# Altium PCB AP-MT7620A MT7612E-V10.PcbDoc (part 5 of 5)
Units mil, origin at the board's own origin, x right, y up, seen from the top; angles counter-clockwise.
Board outline 4645.67 x 3740.16 mil, 4 copper layers (Top, Inner Layer 2, Inner Layer 3, Bottom), stack 35.4 mil thick; 603 components, 409 nets, 1850 pads, 2004 vias.
Unrouted connection lines stored in the file: 90.
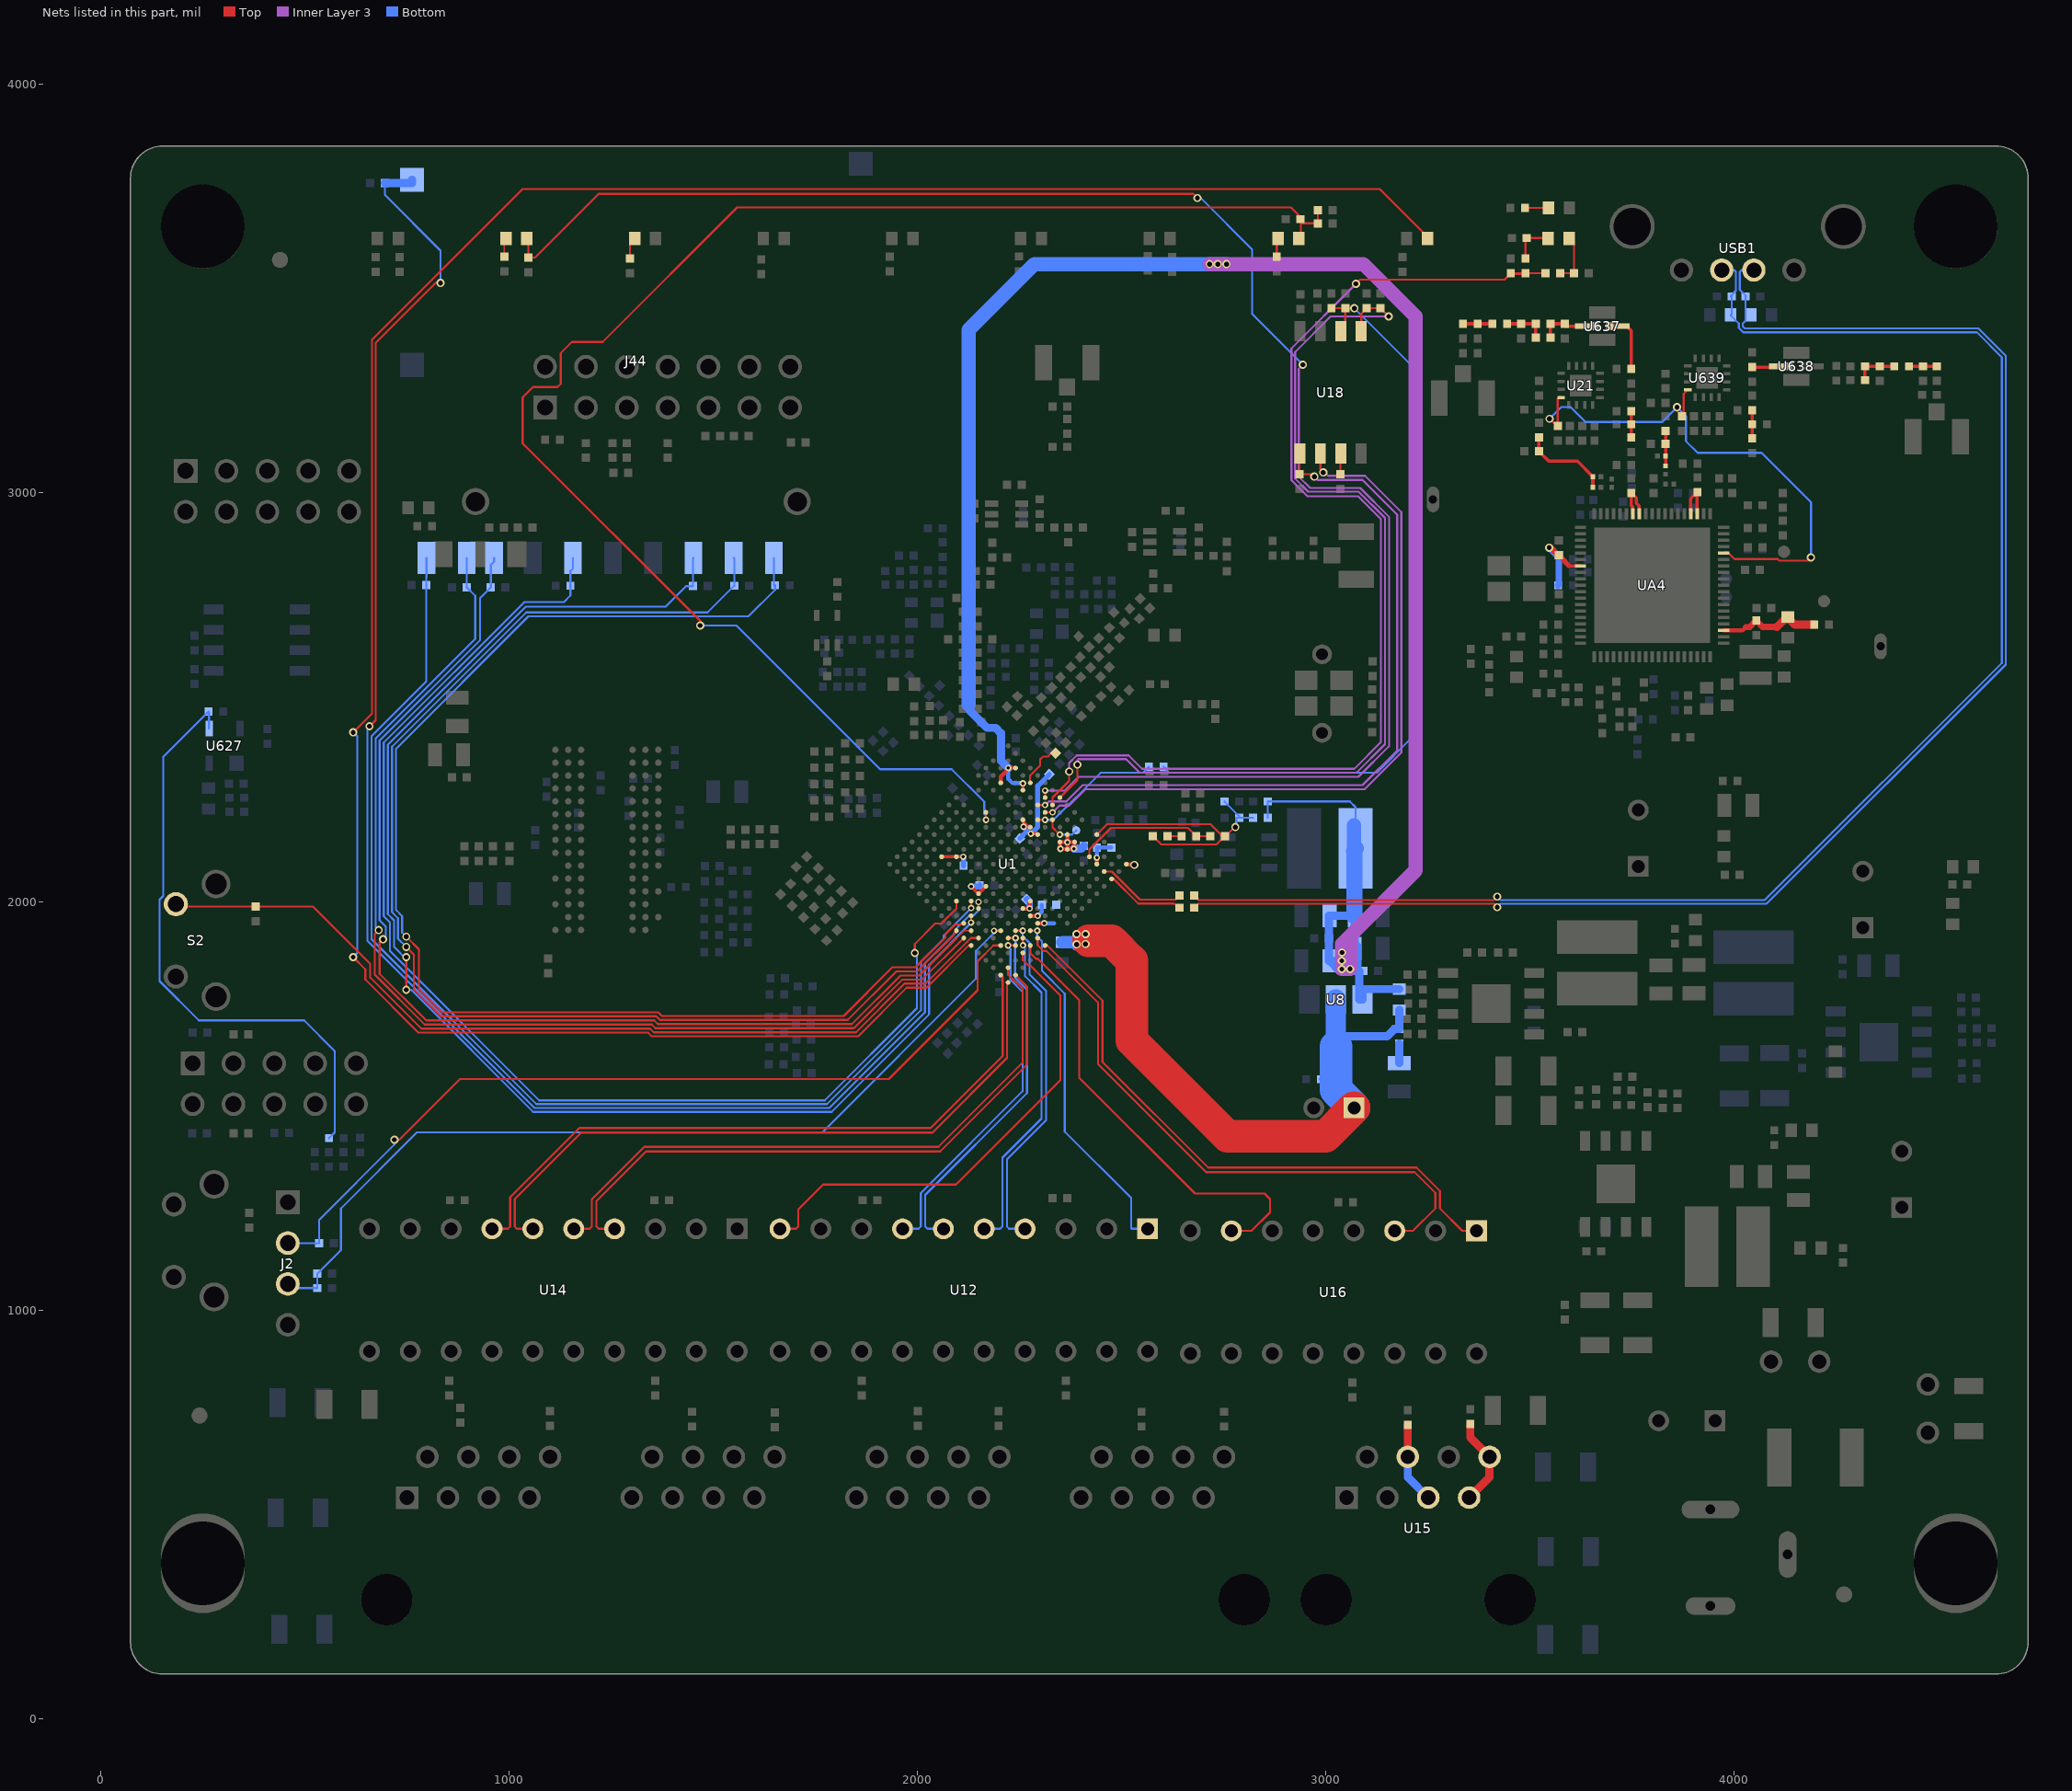
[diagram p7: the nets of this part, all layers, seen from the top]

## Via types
v1: diameter 20, hole 12, Top to Bottom, 1824 vias
v2: diameter 16, hole 8, Top to Bottom, 180 vias

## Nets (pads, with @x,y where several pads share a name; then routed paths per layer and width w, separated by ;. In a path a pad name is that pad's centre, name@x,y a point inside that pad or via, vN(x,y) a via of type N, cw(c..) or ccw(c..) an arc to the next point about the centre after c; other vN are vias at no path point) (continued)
RXIP2: U1.P16 U12.10 | length 1213.5
  Top w5: U12.10@1664,1199 1703,1199 1708.5,1204.5 1708.5,1246.28 1769.68,1307.45 2094.68,1307.45 2350.25,1563.03 2350.25,1769.97 2277.93,1842.29 2273.21,1842.29 2258.69,1856.81 U1.P16@2258.69,1874.36
RXIP3: U1.M15 U12.1 | length 881.4
  Top w5: U1.M15@2276.79,1928.64 v2(2293.72,1928.64)
  Bottom w5: v2(2293.72,1928.64) 2293.72,1913.94 2305.19,1902.47 2305.19,1830.54 2361.26,1774.47 2361.26,1748.84 2361.25,1436.81 2523.71,1274.35 2523.71,1200.29 2525,1199 U12.1@2564,1199
RXIP4: U1.N16 U16.7 | length 1111.7
  Top w5: U1.N16@2276.79,1892.45 2276.79,1874.09 2290.78,1860.09 2295.13,1860.09 2396.25,1758.97 2396.25,1568.97 2680.1,1285.12 2850.1,1285.12 2863.5,1271.72 2863.5,1239.09 2818.41,1194 U16.7@2769,1194
S_COMP: C37.2 R26.1 | length 34
  Top w5: R26.1@2613,2160 C37.2@2647,2160
SD_CD: J44.CD R388.2 U1.P9 | length 2914.9
  Top w5: v2(2132,1984) U1.P9@2132.02,2001.02
  Bottom w5: R388.2@798.61,2775.61 R388.2@798,2775 ; J44.CD@798.61,2841 798.61,2793.62 798,2793.01 R388.2@798,2775 ; v2(2132,1984) 2065,1917 2065,1909 2009,1853 2009,1734 1779.34,1504.34 1067.66,1504.34 664,1908 664,2405 798,2539 R388.2@798,2775
SD_CLK: C275.1 J44.5 U1.R8 | length 3066.7
  Top w5: v1(1994,1874) 1994,1896.03 2043.85,1945.88 2058.88,1945.88 2095.83,1982.83 U1.R8@2095.83,2001.02
  Bottom w5: J44.5@1156.87,2841 1156.87,2814.87 1151,2809 C275.1@1151,2773 1151,2749 1135.08,2733.08 1038.08,2733.08 694,2389 694,1964 709,1949 709,1879 1074.57,1513.43 1773.43,1513.43 1999,1739 1999,1869 v1(1994,1874)
SD_CMD: J44.2 R377.2 U1.R10 | length 3391.9
  Top w5: v1(749,1784) v1(749,1864) ; v2(2131.9,1948.5) U1.R10@2132.02,1964.83
  Bottom w5: v1(749,1784) 761.24,1784 1059.92,1485.32 1790.32,1485.32 2029,1724 2029,1845.6 v2(2131.9,1948.5) ; v1(749,1864) 749,1859 719,1889 719,1954 704,1969 704,2384 1041.87,2721.87 1384.1,2721.87 1434.23,2772 R377.2@1451,2772 1451,2839.85 J44.2@1452.15,2841
SD_D0: J44.7 R376.2 U1.T11 | length 2740
  Top w4: 2096,1910 2115,1928.64 U1.T11@2132.02,1928.64
  Top w5: v1(692.04,1907.46) 684,1899.42 684,1823 798,1709 1356,1709 1365,1700 1840,1700 1959,1819 2005,1819 2096,1910
  Bottom w5: v1(692.04,1907.46) 699,1914.42 699,1939 684,1954 684,2394 930,2640 930,2743 R376.2@956,2769 956,2824 963.96,2831.96 J44.7@963.96,2841
SD_D1: J44.8 R375.2 U1.U11 | length 2724.7
  Top w5: v1(681.64,1930.04) 671.71,1920.11 671.71,1821.29 794,1699 1350,1699 1359,1690 1845,1690 1964,1809 2012.38,1809 U1.U11@2113.93,1910.55
  Bottom w5: v1(681.64,1930.04) 674,1937.68 674,2399 918,2643 918,2748 R375.2@897,2769 897,2790.3 ; 897.03,2790.33 J44.8@897.03,2841
SD_D2: J44.9 R371.2 U1.T10 | length 3243
  Top w5: v1(749,1914) 780,1883 780,1785.65 836.65,1729 1366,1729 1375,1720 1820,1720 1939,1839 1996,1839 2069,1912 2069,1920 2093,1944 2113.93,1944 U1.T10@2113.93,1946.74
  Bottom w5: v1(749,1914) 739,1924 739,1964 724,1979 724,2374 1047.82,2697.82 1586.82,2697.82 1652,2763 R371.2@1652,2774 1649,2774 J44.9@1649,2841
SD_D3: J44.1 R373.2 U1.U10 | length 3137.9
  Top w5: v1(749,1889) 767.36,1870.64 767.36,1785.55 833.91,1719 1361,1719 1370,1710 1830,1710 1949,1829 2000.01,1829 2089,1918 2089,1921.81 U1.U10@2095.83,1928.64
  Bottom w5: v1(749,1889) 729,1909 729,1959 714,1974 714,2379 1042.6,2707.6 1486.6,2707.6 R373.2@1552,2773 1552,2839.57 J44.1@1550.57,2841
SD_WP: J44.WP R389.2 U1.P10 | length 4043.8
  Top w5: v1(659,2429) 659.23,2429 674,2443.77 674,3367 821,3514 v1(833,3514) ; v2(2150,1999) 2150.12,1998.88 U1.P10@2150.12,1982.93
  Bottom w5: v1(659,2429) 654,2424 654,1904 1063.21,1494.79 1784.79,1494.79 2018.9,1728.9 2018.9,1849.2 2095.7,1926 2095.7,1933.7 2128.25,1966.25 2138.25,1966.25 2150,1978 v2(2150,1999) ; R389.2@697,3758.5 697,3729 833,3593 v1(833,3514)
  Bottom w20: R389.2@697,3758.5 763.17,3758.5 J44.WP@763.17,3766.2
SECLED: D20.1 R370.1 R824.2 | length 104.9
  Top w5: R824.2@3489,3574 3489,3621 R370.1@3492,3624 3540.47,3624 3540.47,3622.78 D20.1@3544.41,3622.78
SECU_LED: D20.2 R823.2 R825.1 | length 126.2
  Top w5: R823.2@3574,3538 R825.1@3608,3538 3608,3614.31 3599.53,3622.78 D20.2@3595.59,3622.78
SFLASH_CLK: SR1.1 U1.D8 | length 326
  Top w5: U1.D8@2294.88,2200.04 v2(2313.13,2200)
  Bottom w5: v2(2313.13,2200) 2333.6,2200 2448.64,2315.04 2552.04,2315.04 SR1.1@2567,2330
SMPS_3V3_IN: CA36.1 CA37.1 RA21.1 UA4.41 | length 257.7
  Top w10: UA4.41@3974.2,2663.76 4020.68,2663.76 4028.19,2671.27
  Top w15: 4028.19,2671.27 4028.63,2671.71 4038.02,2671.71 4054,2687.69 4054,2687.56 CA36.1@4054.14,2687.56 4069.46,2672.23 4104.67,2672.23
  Top w20: 4104.67,2672.23 4129.16,2696.73 CA37.1@4131.16,2696.73 4131.16,2694.58 4131.01,2694.58 4147.59,2678 RA21.1@4196,2678
SOC_1.2VD: C7.1 C42.1 C43.1 C44.1 C50.1 C72.1 C166.1 C167.1 C210.1 R23.1 R55.1 R829.1 R830.1 U1.A17 U1.C11 U1.C12 U1.D11 U1.D12 U1.E7 U1.E8 U1.E9 U1.K13 U1.L13 U1.L14 U1.L15 U1.M5 U1.M9 U1.N4 U1.N9 U8.2 | length 2368.2
  Top w5: U1.L14@2276.79,1964.83 2277.24,1965.28 U1.L14@2277.75,1965.28
  Top w8: U1.N4@2059.64,2109.6 U1.M5@2095.83,2109.6 2112.4,2109.6 v2(2112.5,2109.5) ; v2(2132,2037) 2131.24,2037 2131.64,2036.62 U1.N9@2150.12,2019.12 U1.M9@2168.21,2037.21 ; U1.E7@2258.69,2200.07 2261,2197.76 2261,2194 ; U1.E8@2276.79,2181.98 2275.76,2183 U1.E8@2272,2183 ; v2(2278,2166) 2292.76,2166 U1.E9@2294.88,2163.88 ; U1.L15@2294.88,1946.74 U1.L15@2294.88,1946.87 ; v2@2311,1946.87 v2(2311,1947) ; 2261,2194 U1.E8@2272,2183 ; 2261,2194 v2(2260.3,2183) U1.E8@2272,2183
  Top w10: U1.L13@2258.69,1982.96 v2(2275,1983) ; v2(2275,1983) 2275.89,1983 2275.89,2001.02 U1.K13@2276.79,2001.02 ; U1.L14@2276.79,1964.83 2286.19,1964.83 2286.36,1965 v2(2295,1965) ; U1.L15@2294.88,1946.87 v2@2311,1946.87 ; U1.C11@2367.26,2163.88 2367.4,2163.88 v2@2367.4,2145.39 ; U1.A17@2512.02,2091.5 2512.02,2090.49 2531.33,2090.49 v1(2531.33,2089.48) ; U1.D11@2349.89,2145.39 2349.89,2129.09 v2(2350.61,2129.09) 2350.61,2128.39 U1.D12@2367.26,2128.39 ; U1.D11@2349.89,2145.39 2349.17,2145.39 U1.D11@2349.17,2145.79 2349.89,2145.79 U1.D11@2349.89,2145.39 ; U1.D11@2349.89,2145.39 v2@2367.4,2145.39 ; U1.D12@2367.26,2128.39 U1.D12@2367.26,2127.69 2367.4,2127.69 U1.D12@2367.4,2128.52 ; U1.D12@2367.26,2128.39 2367.26,2128.52 U1.D12@2367.4,2128.52 ; U1.D12@2367.4,2128.52 2383.56,2128.52 v2(2383.56,2129.35) 2384.46,2129.35 U1.C12@2384.46,2145.39 ; U1.D12@2367.4,2128.52 v2@2367.4,2144.99 ; v2@2367.4,2144.99 v2@2367.4,2145.39 ; v2@2367.4,2144.99 v2(2367.55,2144.99) v2@2367.55,2145.39 ; v2@2367.4,2145.39 v2@2367.55,2145.39 ; v2@2367.55,2145.39 U1.C12@2384.46,2145.39 ; U1.C12@2384.46,2145.39 2384.46,2145.79 U1.C12@2385.36,2145.79 2385.36,2145.39 U1.C12@2384.46,2145.39
  Top w20: v1(2412,1896) 2412,1897 2419.21,1904.21
  Top w80: 2419.21,1904.21 2475.92,1904.21 2525,1855.13 2525,1660 2760,1425 2999.21,1425 C7.1@3069.21,1495
  Bottom w10: v2(2295,1965) 2305,1975 C167.1@2305,1992 ; v2(2311,1947) 2335,1947 ; C50.1@2988,1565 3009.77,1543.23 3020.98,1543.23 3025,1539.21
  Bottom w12: v2(2112.5,2109.5) 2113.5,2108.5 C72.1@2113.5,2087.5 ; C44.1@2251.23,2154.27 2270,2173.04 2270,2174 ; v2(2260.3,2183) 2270,2174 ; R23.1@2323.27,2311.27 2294.87,2282.87 2294.87,2182.87 v2(2278,2166) 2270,2174
  Bottom w15: v2(2132,2037) 2151,2037 C43.1@2152.5,2039.5 ; R55.1@2267.53,2004.93 2268.72,2006.12 2275,1999.85 v2(2275,1983)
  Bottom w20: v2(2383.56,2129.35) 2401.35,2129.35 C210.1@2408,2136 ; 3025,1675 3030,1670 3150,1670 3168,1688 R829.1@3180,1688 R830.1@3180,1734.41
  Bottom w30: C42.1@2355,1900.59 2390,1900.59 v1(2390,1895)
  Bottom w50: 3025,1645 3025,1675 U8.2@3025,1760
  Bottom w80: 3025,1645 3025,1539.21 C7.1@3069.21,1495
  other v1: 2390,1920 2412,1920
SOC_1.5VD: C31.1 C32.1 C33.1 C34.1 C46.1 C55.1 C56.1 C97.1 C103.1 L4.2 R21.1 R830.2 U1.B3 U1.C5 U1.D3 U8.3 | length 5643.6
  Top w8: U1.D3@2203.16,2291.79 U1.D3@2204.4,2290.55 ; v2(2258.6,2289) 2258.69,2288.91 U1.C5@2258.69,2272.45
  Top w10: U1.D3@2204.4,2290.55 2204.4,2305.66 2224.25,2325.51 v2(2223.02,2326.74) U1.B3@2240.6,2326.74
  Inner Layer 3 w30: v1(3039.43,1854.87) 3059.28,1835.02 3059.53,1834.77 v1@3059.65,1834.9
  Inner Layer 3 w35: v1(2715.58,3559.99) v1(2735.59,3559.99) v1(2757,3560) 3092,3560 3220,3432 3220,2076.23 3059.77,1916 ; v1(3039.43,1854.87) 3039.43,1895.66 3059.77,1916 ; v1(3039.43,1854.87) v1(3039.43,1834.8) 3049.49,1834.8 3049.71,1835.02 3059.28,1835.02 v1@3059.53,1835.02 ; v1(3039.43,1854.87) 3039.55,1854.99 3049.59,1844.96 v1@3059.53,1835.02 ; v1@3059.53,1835.02 v1(3059.77,1835.02) ; v1@3059.53,1835.02 3059.65,1834.9 v1(3059.77,1835.02) ; v1(3059.77,1835.02) 3059.77,1916
  Bottom w5: R21.1@2858,2205 C31.1@2858,2245 3058.92,2245 3072.99,2230.93 L4.2@3072.99,2130 ; v1(3039.43,1834.8) 3041.2,1834.8 v1@3046,1830 ; v1(3039.43,1854.87) v1@3039.55,1854.99 ; v1@3059.65,1834.9 v1(3059.77,1835.02)
  Bottom w10: v2(2223.02,2326.74) 2223.02,2299.95 2233.47,2289.5 2258.6,2289.5 v2(2258.6,2289)
  Bottom w20: 2125.5,2483 2127,2481.5 2127,2469 2171,2425 2192,2425 2205,2412 C103.1@2205,2400 C97.1@2205,2367.5 2205,2344.76 v2(2223.02,2326.74) ; v1(3039.43,1834.8) v1(3039.43,1854.87) C56.1@3009.58,1854.87 ; v1@3039.55,1854.99 v1@3059.65,1834.9 ; R830.2@3180,1785.59 3090,1785.59 U8.3@3090,1760 3082,1760 3082,1830 3077.55,1830 ; C56.1@3009.45,1855 C56.1@3009.58,1854.87 ; C56.1@3009.45,1855 3008,1855 C32.1@3008,1910 3008,1965 C33.1@3009.45,1965 C46.1@3070.55,1965 C34.1@3070.55,1885 3077.55,1885 3077.55,1830 ; C56.1@3009.45,1855 3009.45,1854.87 C56.1@3009.58,1854.87 ; C56.1@3009.58,1854.87 3034.45,1830 3046,1830 3077.55,1830
  Bottom w35: 2125.5,2483 2125.5,3398.71 2286.79,3560 v1(2715.58,3559.99) v1(2735.59,3559.99) v1(2757,3560) ; L4.2@3069.5,2186 L4.2@3069.5,2125.34 ; C34.1@3070.5,1884.95 C34.1@3070.55,1885 C34.1@3071.55,1886 ; L4.2@3072.99,2130 3070.55,2126.75 L4.2@3069.5,2125.34 ; L4.2@3069.5,2125.34 3066.99,2122 3069.5,2124.51 L4.2@3069.5,2125.34
  Bottom w40: C46.1@3070.55,1965 3070.55,2126.75 3070.55,2127.56 L4.2@3072.99,2130
  other v1: 3040,1875
SOC_COMP: C37.1 C38.1 U1.C14 | length 343.6
  Top w5: U1.C14@2421.55,2109.6 2421.55,2127.55 2474.17,2180.17 2662.83,2180.17 C37.1@2683,2160 C38.1@2717,2160
SOC_FB: C38.2 R21.2 R22.2 R24.1 R26.2 U1.A13 | length 686.5
  Top w5: U1.A13@2439.64,2163.88 2464.93,2189.17 2718,2189.17 2747.17,2160 C38.2@2753,2160 ; R26.2@2577,2160 2597,2140 2733,2140 C38.2@2753,2160 ; v1(2778.86,2182.19) 2777.94,2183.11 2753.92,2159.08 2753,2159.08 C38.2@2753,2160
  Bottom w5: R22.2@2752,2245 2788,2209 R24.1@2788,2205 ; v1(2778.86,2182.19) 2781.15,2182.19 2781.15,2205 R24.1@2788,2205 ; R21.2@2822,2205 R24.1@2788,2205
SPI_CLK: R125.2 R127.2 SR1.2 U18.6 | length 1874.3
  Top w5: R125.2@3014,3452 R127.2@3048,3452 ; U18.6@3037,3395.8 3048,3406.8 R127.2@3048,3452 ; v1(3070,3452) R127.2@3048,3452
  Bottom w5: SR1.2@2603,2330 2618,2315 3125,2315 3209,2399 3209,3313 v1(3070,3452)
SPI_CS0: R170.1 U1.C7 U18.1 | length 1843.3
  Top w5: U1.C7@2294.88,2236.26 2294.88,2236.18 2313.14,2236.18 v2(2313.14,2236.11) ; U18.1@2937,3096.2 2936,3095.2 R170.1@2936,3046 2966,3046 v1(2972,3040)
  Inner Layer 3 w5: v2(2313.14,2236.11) 2322.04,2245 2365,2245 2405,2285 3090,2285 3175,2370 3175,2946.91 3089.91,3032 2980,3032 v1(2972,3040)
SPI_CS1: TP601.1 U1.C9 | length 88.7
  Top w5: U1.C9@2331.07,2200.07 2331.07,2181.5 2345.57,2167 2349,2165.07 v2(2349,2164)
  Bottom w5: v2(2349,2164) 2379.13,2164 TP601.1@2389.39,2174.26
SPI_HOLD: R142.2 R823.1 R824.1 U1.B8 | length 2792.2
  Top w5: U1.B8@2331.07,2236.26 2331.07,2254.36 2372,2295.29 v1(2372,2318) ; v1(3074,3512) 3084,3522 3438,3522 3452,3536 3487,3536 R824.1@3489,3538 ; R142.2@3453,3538 R824.1@3489,3538 ; R823.1@3538,3538 R824.1@3489,3538
  Inner Layer 3 w5: v1(2372,2318) 2372,2339 2390.53,2357.53 2517.47,2357.53 2550,2325 3070,2325 3135,2390 3135,2936 3079,2992 2955.27,2992 2916,3031.27 2916,3354 v1(3074,3512)
SPI_MISO: U1.C8 U18.2 | length 1801.1
  Top w5: U1.C8@2312.98,2218.17 2314.81,2218.2 v2(2331.2,2218.2) ; U18.2@2987,3096.2 2987,3057 v1(2994,3050)
  Inner Layer 3 w5: v2(2331.2,2218.2) 2348,2235 2371.8,2235 2411.8,2275 3095,2275 3185,2365 3185,2953 3096,3042 3006,3042 2998,3050 v1(2994,3050)
SPI_MOSI: R133.2 R135.2 U1.A8 U18.5 | length 2423.8
  Top w5: U1.A8@2349.17,2254.36 2392,2297.19 v1(2392,2335) ; U18.5@3082,3395.8 U18.5@3087,3395.8 3087,3439 R135.2@3100,3452 R133.2@3134,3452 v1(3154,3432)
  Inner Layer 3 w5: v1(2392,2335) 2392,2345.93 2394.58,2348.51 2511.49,2348.51 2545,2315 3075,2315 3145,2385 3145,2938.73 3080.73,3003 2957,3003 2925,3035 2925,3345 3012,3432 v1(3154,3432)
SPI_WP: D26.2 R136.2 U1.B7 | length 4282.8
  Top w5: D26.2@1044.47,3622.78 1048.41,3622.78 1048,3622.37 R136.2@1048,3576 1064,3576 1220,3732 2676,3732 v1(2686,3722) ; U1.B7@2312.98,2254.36 2313.08,2254.36 2313.08,2271.57 v2(2313.18,2271.57)
  Inner Layer 3 w5: v2(2313.18,2271.57) 2324.05,2271.57 2324.12,2271.5 2361.5,2271.5 2395,2305 3080,2305 3155,2380 3155,2941.46 3084.46,3012 2962,3012 2934,3040 2934,3304 v1(2944,3314)
  Bottom w5: v1(2686,3722) 2694,3722 2820,3596 2820,3438 v1(2944,3314)
TRSW_P: C159.2 C161.2 U21.4 U639.4 UA4.53 | length 1381.5
  Top w5: v1(3547.97,3181.47) 3564.93,3164.51 3567.49,3164.51 C159.2@3568,3164 3568,3230.62 3570.85,3233.47 3571.47,3233.47 U21.4@3570,3232 ; v1(3860,3210) 3858,3210 3858,3202 C161.2@3872,3188 3876.47,3192.47 3876.47,3202.53 3876.42,3202.58 3876.42,3242.63 U639.4@3886.26,3252.47 ; UA4.53@3974.2,2852.74 3974.2,2854 3984.9,2854 4000.9,2838 4106.29,2838 4110.29,2834 4180,2834 v1(4188,2842)
  Top w8: U21.4@3571.47,3233.47 U21.4@3576.26,3233.47
  Bottom w5: v1(3547.97,3181.47) 3576.49,3210 3600,3210 3636.13,3173.87 3823.87,3173.87 v1(3860,3210) 3882,3188 3882,3126.67 3910.67,3098 4067,3098 4188,2977 v1(4188,2842)
TXOM0: U1.U17 U14.6 | length 1649.9
  Top w5: U14.6@1059,1199 1020,1199 1014.5,1204.5 1014.5,1271.72 1177.45,1434.67 2037.45,1434.67 2220,1617.22 2220,1801.98 U1.U17@2222.5,1801.98
TXOM1: U1.T17 U14.4 | length 1532.6
  Top w5: U14.4@1259,1199 1220,1199 1214.5,1204.5 1214.5,1266.72 1336.15,1388.37 2056.15,1388.37 2268.81,1601.03 2268.81,1791.97 2240.65,1820.13 U1.T17@2240.6,1820.07
TXOM2: U1.P15 U12.7 | length 872.1
  Top w5: v2(2222.45,1892.55) 2231.1,1892.55 2231.19,1892.45 U1.P15@2240.6,1892.45
  Bottom w5: U12.7@1964,1199 2003,1199 2008.5,1204.5 2008.5,1286.6 2257.83,1535.93 2257.83,1779.19 2228.5,1808.52 2228.5,1883.75 2221.08,1891.18 v2(2222.45,1892.55)
TXOM3: U1.N14 U12.4 | length 851.9
  Top w5: U1.N14@2240.6,1928.64 2250,1928.64 v2(2258.4,1928.65)
  Bottom w5: v2(2258.4,1928.65) 2258.4,1915.38 2275,1898.78 2275,1821.79 2315.23,1781.56 2315.23,1464.23 2219.5,1368.5 2219.5,1204.5 2225,1199 U12.4@2264,1199
TXOM4: U1.M17 U16.1 | length 1458.4
  Top w5: U1.M17@2312.98,1892.45 2318.33,1892.45 2453.46,1757.32 2453.46,1607.32 2712.05,1348.73 3222.05,1348.73 3279.5,1291.28 3279.5,1249 3334.5,1194 U16.1@3369.39,1194
TXOP0: U1.U16 U14.7 | length 1667.4
  Top w5: U14.7@959,1199 998,1199 1003.5,1204.5 1003.5,1276.28 1172.89,1445.67 2032.89,1445.67 2209,1621.78 2209,1815.48 U1.U16@2204.4,1820.07
TXOP1: U1.T16 U14.5 | length 1554.8
  Top w5: U14.5@1159,1199 1198,1199 1203.5,1204.5 1203.5,1271.28 1331.59,1399.37 2051.59,1399.37 2257.81,1605.59 2257.81,1787.41 2239.78,1805.44 2237.68,1805.44 2222.5,1820.62 U1.T16@2222.5,1838.17
TXOP2: U1.P14 U12.6 | length 887
  Top w5: U1.P14@2222.5,1910.55 v2(2240.73,1910.55)
  Bottom w5: U12.6@2064,1199 2025,1199 2019.5,1204.5 2019.5,1282.04 2268.83,1531.37 2268.83,1783.76 2239.5,1813.09 2239.5,1889.05 2240.73,1890.28 v2(2240.73,1910.55)
TXOP3: U1.N15 U12.5 | length 811.3
  Top w5: U1.N15@2258.69,1910.55 2258.69,1897.51 2258.83,1897.36 v2(2258.83,1892.73)
  Bottom w5: U12.5@2164,1199 2203,1199 2208.5,1204.5 2208.5,1373.06 2304.23,1468.79 2304.23,1777 2264,1817.23 2264,1887.56 v2(2258.83,1892.73)
TXOP4: U1.M16 U16.3 | length 1490.2
  Top w5: U1.M16@2294.88,1910.55 2294.88,1893 2308.75,1879.14 2316.09,1879.14 2442.45,1752.77 2442.45,1602.77 2707.49,1337.73 3217.49,1337.73 3268.5,1286.72 3268.5,1249 3213.5,1194 U16.3@3169,1194
UART_RX: J2.2 R54.1 U1.R14 | length 2129.2
  Top w5: v1(720,1417) 732,1417 880.5,1565.5 1928.23,1565.5 1928.3,1565.57 1930.57,1565.57 2147.69,1782.69 2147.69,1853.69 2186.46,1892.46 U1.R14@2204.41,1892.46
  Bottom w5: J2.2@459,1164 R54.1@536,1164 536,1221 720,1405 v1(720,1417)
UART_TX: J2.3 R137.2 R139.2 U1.P13 | length 2237.9
  Top w5: v2(2188,1928.5) U1.P13@2204.4,1928.64
  Bottom w5: J2.3@459,1064 459,1059 464,1054 R139.2@531,1054 R137.2@531,1089 589,1147 589,1249 775,1435 1767.74,1435 2144,1811.26 2144,1879 2188,1923 v2(2188,1928.5)
UPHY0_PADM: R815.2 U1.C16 | length 217.4
  Top w5: U1.C16@2457.74,2073.4 2476.33,2073.4 2544.99,2004.75 2632.5,2004.75 2642,2014.25 R815.2@2642,2015
UPHY0_PADM_0: D3.2 R815.1 UC1.1 USB1.2 | length 3840.9
  Top w5: R815.1@2678,2015 2689.31,2003.69 3333.81,2003.69 3333.87,2003.75 3411.75,2003.75 v1(3420,2012)
  Bottom w5: v1(3420,2012) 3428.25,2003.75 4075.03,2003.75 4655.25,2583.97 4655.25,3332.07 4594.21,3393.1 4022.18,3393.1 4011.25,3404.03 4011.25,3414.5 3992,3433.75 D3.2@3992,3435.59 ; USB1.2@3969.4,3545.58 3969.67,3545.62 3999.67,3545.62 4004.29,3541 4004.29,3494.83 3992.23,3482.77 3992.23,3481 UC1.1@3994,3481 3994,3437.59 D3.2@3992,3435.59 ; D3.2@3991.59,3436 D3.2@3992,3435.59
UPHY0_PADP: R814.2 U1.C17 | length 197.4
  Top w5: U1.C17@2475.83,2055.31 2480.99,2055.31 2541.05,1995.25 2628.71,1995.25 2640.48,1983.48 2642,1983.48 R814.2@2642,1985
UPHY0_PADP_0: D4.2 R814.1 UC2.1 USB1.3 | length 3849.8
  Top w5: R814.1@2678,1985 2687.19,1994.19 3356.68,1994.19 3356.74,1994.25 3411.75,1994.25 v1(3420,1986)
  Bottom w5: v1(3420,1986) 3428.25,1994.25 4078.97,1994.25 4664.75,2580.03 4664.75,3336 4598.15,3402.6 4026.11,3402.6 4020.75,3407.97 4020.75,3414.5 4028,3421.75 UC2.1@4028,3481 4029.09,3481 4029.09,3482.09 4013.79,3497.4 4013.79,3541 4018.41,3545.62 USB1.3@4048.41,3545.62
UPHY0_VRES: C69.2 R51.1 U1.C15 | length 75.9
  Top w10: U1.C15@2439.64,2091.5 v2(2439.62,2107.43)
  Bottom w10: v2(2439.62,2107.43) 2439.62,2132 C69.2@2440,2132 R51.1@2475,2132
USB_IND_LED: D13.2 U1.U12 | length 6033.6
  Top w5: v1(619,1864) 649,1834 649,1809 779,1679 1341,1679 1350,1670 1855,1670 1974,1789 2022.66,1789 2126.11,1892.45 U1.U12@2132.02,1892.45 ; v1(619,2414) 665,2460 665,3375 1034,3744 3131.92,3744 3253.14,3622.78 D13.2@3249.2,3622.78
  Bottom w5: v1(619,1864) 629,1874 629,2404 v1(619,2414)
V12: C48.1 R829.2 | length 47.6
  Bottom w20: C48.1@3180,1604.45 R829.2@3180,1652 R829.2@3180.05,1651.95
WAN_C1: R122.1 U15.4 U15.5 | length 198.7
  Top w20: U15.4@3201,641 R122.1@3201,719
  Bottom w20: U15.4@3201,641 3201,591 U15.5@3251,541
WAN_C2: R123.1 U15.7 U15.8 | length 220.2
  Top w20: U15.7@3351,541 3401,591 U15.8@3401,641 3354,688 R123.1@3354,721
WANLED: D12.1 R167.1 | length 55.7
  Top w4: R167.1@1297,3574 1297,3615.47 1304.31,3622.78 D12.1@1308.25,3622.78
WDT_RST_N: R896.2 R907.1 U627.3 | length 1470.2
  Bottom w5: U627.3@266.2,2423.32 266.2,2463.8 R896.2@265,2465 154,2354 154,2013.53 145,2004.53 145,1805.47 241.47,1709 499,1709 574,1634 574,1435 R907.1@560,1421
WF0_RF_5G_RX_AUXIN: C77.1 C78.1 R161.2 R172.2 | length 217.7
  Top w8: R172.2@3522,3136 R161.2@3522,3102 3546,3078 3616,3078 C77.1@3654,3040 C78.1@3654,3014
WF0_RF_5G_TR: CA77.2 UA4.69 UA4.70 | length 111.2
  Top w8: UA4.70@3751.76,2949.2 3751.76,2965.43 3748,2969.19 CA77.2@3748,3000 3760.35,2987.65 3760.35,2974.98 3767.5,2967.83 UA4.69@3767.5,2949.2
WF0_RF_5G_TR_1: CA27.2 CA30.2 LA13.2 R868.2 U637.2 | length 149
  Top w8: CA30.2@3550,3380 CA27.2@3550,3414 LA13.2@3585,3414 3585,3408 U637.2@3628.77,3408 R868.2@3659,3408
WF0_RF_5G_TRX: CA25.1 CA27.1 CA28.1 CA30.1 | length 104
  Top w8: CA25.1@3444,3414 CA28.1@3478,3414 CA27.1@3514,3414 CA30.1@3514,3380
WF0_RF_5G_TRX_SW: C1064.2 CA80.2 R868.1 U637.4 | length 150.6
  Top w8: R868.1@3695,3408 U637.4@3725.23,3408 3737.04,3408 3748,3397.04 CA80.2@3748,3304
WF0_RF_5G_TX: C1065.1 CA23.1 CA24.1 CA79.1 | length 64
  Top w8: CA23.1@3748,3136 CA24.1@3748,3168 CA79.1@3748,3200
WF1_RF_5G_RX_AUXIN: C79.1 C1063.1 R174.2 R175.2 | length 86
  Top w8: C79.1@3832,3066 C1063.1@3832,3090 R174.2@3832,3120 R175.2@3832,3152
WF1_RF_5G_TR: CA81.1 UA4.60 UA4.61 | length 111.7
  Top w8: UA4.61@3893.49,2949.2 3893.49,2985.49 CA81.1@3909.24,3001.24 ; UA4.60@3909.24,2949.2 CA81.1@3909.24,3001.24 ; CA81.1@3910,3002 CA81.1@3909.24,3001.24
WF1_RF_5G_TRX: CA26.1 CA31.2 CA33.2 LA14.2 | length 106
  Top w8: CA33.2@4320,3276 CA31.2@4320,3310 LA14.2@4356,3310 CA26.1@4392,3310
WF1_RF_5G_TRX_SW: C179.2 CA82.2 R869.2 U638.2 | length 92
  Top w8: CA82.2@4044,3308 4103.77,3308 U638.2@4103.77,3310 R869.2@4134,3310
WF1_RF_5G_TX: C1066.1 CA21.1 CA22.1 CA46.1 | length 68
  Top w8: CA21.1@4044,3134 CA22.1@4044,3168 CA46.1@4044,3202
WF_XO_1V5: CA38.1 CA40.1 RA20.1 UA4.7 | length 240.3
  Top w5: v1(3547,2866) 3565,2848 3568,2848 3569.5,2846.5 3569.5,2847.58 CA38.1@3569.5,2848
  Top w8: 3594.82,2822.15 3595.73,2821.24 UA4.7@3623.8,2821.24
  Top w12: CA38.1@3570.69,2848 3570.69,2847.69 3585.98,2832.41 3585.98,2830.99 3594.82,2822.15
  Top w15: v1(3547,2866) 3549.04,2868.04 CA38.1@3569.08,2848 ; CA38.1@3568,2848 CA38.1@3569.08,2848 ; CA38.1@3571,2848 3570.69,2848 CA38.1@3570.04,2848 ; CA38.1@3569.08,2848 3569.5,2847.58 3570.04,2847.04 CA38.1@3570.04,2848 ; CA38.1@3569.08,2848 3569.5,2848 CA38.1@3570.04,2848
  Bottom w15: v1(3547,2866) 3565.96,2847.04 CA40.1@3571,2847.04
  Bottom w16: RA20.1@3569,2774 3571,2776.67 3571,2847.04 CA40.1@3571,2848
WLAN_LED: C847.1 D6.2 R132.2 R134.2 U1.G4 | length 3961.3
  Top w5: v1(1468.72,2675.43) 1468.72,2686.68 1034,3121.4 1034,3234 1059,3259 1119,3259 1127.25,3267.25 1127.25,3342.25 1154.61,3369.61 1229.61,3369.61 1559,3699 2915,3699 2940,3674 2940,3672 C847.1@2938,3670 2939,3664 C847.1@2939,3660 ; v2(2168.2,2200) U1.G4@2168.21,2218.17 ; D6.2@2934.24,3622.78 2938.18,3622.78 2939,3623.6 C847.1@2939,3660 ; R132.2@2981,3692 R134.2@2981,3659 2980,3660 C847.1@2939,3660
  Bottom w5: v1(1468.72,2675.43) 1557.57,2675.43 1909,2324 2084,2324 2160.01,2248.17 2164.02,2244.16 2164.02,2214.36 2168.2,2210.18 v2(2168.2,2200)
WLED: D6.1 R155.1 | length 44.1
  Top w5: R155.1@2880,3583 2880,3621.9 2879.12,3622.78 D6.1@2883.06,3622.78
WLED_5G: D17.1 R156.1 | length 58.8
  Top w5: R156.1@3488,3698 D17.1@3541.47,3698 ; D17.1@3540.47,3699 D17.1@3541.47,3698 ; D17.1@3545.41,3698 D17.1@3541.47,3698
WP: SR2.2 U18.3 | length 50.6
  Top w5: SR2.2@3036,3046 3036,3095.2 U18.3@3037,3096.2
WPS_PBC: R154.2 S2.1 U1.T12 | length 2209.8
  Top w5: S2.1@185,1993.58 190.58,1988 R154.2@380,1988 520,1988 661,1847 661,1814 786,1689 1346,1689 1355,1680 1850,1680 1969,1799 2019.93,1799 2122.38,1901.45 2122.45,1901.45 2131.55,1910.55 U1.T12@2150.12,1910.55
WPSLED+: D26.1 R374.1 | length 48.9
  Top w4: R374.1@989,3578 989,3622.43 989.35,3622.78 D26.1@993.29,3622.78
X00008: CA16.1 CA25.2 LA5.2 | length 72
  Top w8: LA5.2@3336,3414 CA16.1@3372,3414 CA25.2@3408,3414
X00009: CA20.1 CA26.2 LA10.2 | length 68
  Top w8: CA26.2@4428,3310 CA20.1@4462,3310 LA10.2@4496,3310
XTAL_V12A: C104.1 U1.B5 | length 111.1
  Top w5: U1.B5@2276.79,2290.55 2276,2291.33 2276,2308 2300.8,2332.8 2300.8,2347.8 2308,2355 2320.73,2355 2330,2364.27 C104.1@2337.27,2364.27
pads on no net: CA46$2F$NI.1 CA46$2F$NI.2 FM1.1 FM2.1 FM3.1 FM4.1 FM5.1 FM6.1 H1.1 H2.1 H3.1 H4.1 J13.12 J44.H1 J44.H2 L19.1 U1.B15 U1.D14 U1.D15 U1.D16 U1.D17 U1.E14 U1.E15 U1.E16 U1.E17 U1.F14 U1.F15 U1.F16 U1.F17 U1.G14 U1.G15 U1.G16 U1.G17 U1.H14 U1.H15 U1.H16 U1.H17 U1.J14 U1.J15 U1.J16 U1.J17 U1.K14 U1.K15 U1.P8 U1.R9 U1.R11 U1.T8 U1.T9 U1.T13 U1.U8 U1.U9 U13.33 U13.34 U15.9 U15.10 U16.2 U16.6 U16.8 U16.9 U16.11 U16.15 U21.9 U21.10 U21.11 U21.15 U21.16 U22.A2 U22.A8 U22.E2 U22.E8 U22.R3 U22.R7 U632.1 U639.9 U639.10 U639.11 U639.15 U639.16 UA4.1 UA4.2 UA4.3 UA4.4 UA4.5 UA4.11 UA4.12 UA4.13 UA4.16 UA4.17 UA4.47 UA4.51 UA4.52 UA4.57 UA4.64 UA4.65 UA4.66 UA4.73 UA4.75 UA4.76

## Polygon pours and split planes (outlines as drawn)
CHGND on Bottom (solid, remove dead copper, pour order 14): 740,1065 3320,1065 3555,830 3555,109 520,109 520,845
GND on Bottom (solid, remove dead copper, pour order 0): 74,3849.16 4719.67,3849.16 4719.67,109 3622,109 3622,871 3354,1139 724,1139 451,866 451,109 76,109 74,1124
3.3VD on Inner Layer 3 (solid, remove dead copper, pour order 16): 451,85 30,85 30,2140 832,2140 832,1557 1997,1557 2108,1668 2108,2017 2208,2017 2255,1970 2255,1880 2265,1870 2430,1870 2440,1880 2440,1965 2420,1985 2360,1985 2340,2005 2340,2065 2365,2090 2415,2090 2468,2037 2530,2037 2545,2052 2545,2140 2512,2173 2363,2173 2338,2148 2315,2148 2305,2158 2305,2247 4247,2247 4590,2590 4590,3360 4580,3370 3945,3370 3800,3515 3285,3515 3198,3428 2263,3428 1743.78,2908.78 1743.78,2573 832,2573 832,2140 30,2140 30,3940 4765,3940 4765,85 3622.03,85 3622.03,871.08 3354.02,1139.09 724.07,1139.09 451,866.02
1.8VD on Inner Layer 3 (solid, remove dead copper, pour order 12): 840,1563 840,2567 1798,2567 2060,2305 2172.05,2305 2172,2193 2172,2143 2102,2143 2102,1672 1993,1563
GND on Inner Layer 3 (solid, remove dead copper, pour order 8): 2308,2253 2308,2310 2065,2310 1800,2575 1755,2575 1750,2580 1750,2905 2267,3422 3202,3422 3285,3505 3800,3505 3940,3365 4575,3365 4585,3355 4585,2595 4243,2253
SOC_1.2VD on Inner Layer 3 (solid, remove dead copper, pour order 6): 2178,2305 2302,2305 2302,2152 2312,2142 2342,2142 2367,2167 2508,2167 2540,2135 2540,2060 2523,2043 2472,2043 2420,2095 2355,2095 2335,2075 2335,2000 2355,1980 2415,1980 2435,1960 2435,1885 2425,1875 2270,1875 2260,1885 2260,1975 2212,2023 2108,2023 2108,2137 2178,2137
CHGND on Inner Layer 3 (solid, remove dead copper, pour order 2): 520,85 520,845 740,1065 3320,1065 3555,830 3555,85
CHGND on Top (solid, remove dead copper, pour order 10): 740,1065 3320,1065 3555,830 3555,109 520,109 520,845
GND on Top (solid, remove dead copper, pour order 4): 74,3849.16 4719.67,3849.16 4719.67,109 3622,109 3622,871 3354,1139 724,1139 451,866 451,109 74,109
CHGND on Inner Layer 2 (split plane): 3552.45,828.94 3552.45,111.55 522.55,111.55 522.55,843.94 741.06,1062.45 3318.94,1062.45
GND on Inner Layer 2 (split plane): 4663.9,3846.13 4678.23,3840.2 4691.12,3831.58 4702.09,3820.61 4710.71,3807.71 4716.64,3793.39 4717.12,3790.98 4717.12,167.17 4716.64,164.77 4710.71,150.44 4702.09,137.55 4691.12,126.58 4678.23,117.96 4663.9,112.03 4661.5,111.55 3624.55,111.55 3624.55,871 3624.35,871.98 3623.8,872.8 3355.8,1140.8 3354.98,1141.35 3354,1141.55 724,1141.55 723.02,1141.35 722.2,1140.8 448.2,866.8 447.65,865.98 447.45,865 447.45,111.55 132.17,111.55 129.77,112.03 115.44,117.96 102.55,126.58 91.58,137.55 82.96,150.44 77.03,164.77 76.55,167.17 76.55,3790.99 77.03,3793.39 82.96,3807.71 91.58,3820.61 102.55,3831.58 115.44,3840.2 129.77,3846.13 132.18,3846.61 4661.49,3846.61

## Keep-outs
Top:
  region: 3841.86,3286.89 3846.69,3286.89 3846.69,3263.76 3841.86,3263.76 3841.86,3286.89
  region: 3960,2644 3992,2644 3992,2651 3956,2651 3956,2603 3956.3,2603 3956.3,2596.57 4012.06,2596.57 4012.06,2627 4008,2627 4008,2603 3970,2603 3970,2602.69 3960,2602.69 3960,2644
  region: 2350.77,2910.09 2354.4,2910.09 2354.4,2883.15 2350.77,2883.15 2350.77,2910.09
  region: 2743.08,2838.75 2772.99,2838.75 2772.99,2811.24 2743.08,2811.24 2743.08,2838.75
  region: 1623.95,2168.69 1628.8,2168.69 1628.8,2142.31 1623.95,2142.31 1623.95,2168.69
  region: 2909.09,2862.07 2936.3,2862.07 2936.3,2832.16 2909.09,2832.16 2909.09,2862.07
  region: 3667.73,3396.61 3688.23,3396.61 3688.23,3393 3667.73,3393 3667.73,3396.61
  region: 2528.53,2745.65 2513.84,2730.96 2535.1,2709.7 2550.48,2725.08 2529.25,2746.31 2528.53,2746.31 2528.53,2745.65
  region: 2168.76,2870.82 2198.56,2870.82 2198.56,2846.07 2168.76,2846.07 2168.76,2870.82
  region: 4029.18,3127.78 4032.72,3127.78 4032.72,3108.24 4029.18,3108.24 4029.18,3127.78
  region: 3418.21,3428.97 3435.15,3428.97 3435.15,3425.44 3418.21,3425.44 3418.21,3428.97
  region: 3720.07,3190.01 3740.15,3190.01 3740.15,3185.04 3720.07,3185.04 3720.07,3190.01
  region: 3733.05,3294.2 3735.78,3294.2 3735.78,3276.94 3733.05,3276.94 3733.05,3294.2
  region: 3733.18,3027.19 3736.72,3027.19 3736.72,3007.65 3733.18,3007.65 3733.18,3027.19
  region: 2192.09,2857.46 2225.39,2857.46 2225.39,2827.44 2192.09,2827.44 2192.09,2857.46
  region: 2695.46,2860.76 2727.83,2860.76 2727.83,2830.96 2695.46,2830.96 2695.46,2860.76
  region: 3385,2850 3539,2850 3539,2728 3385,2728 3385,2850
  region: 4029.03,3230.42 4032.57,3230.42 4032.57,3210.88 4029.03,3210.88 4029.03,3230.42
  region: 2379.53,2909.79 2384.36,2909.79 2384.36,2886.66 2379.53,2886.66 2379.53,2909.79
  region: 3644,2817 3538.25,2817 3538.25,2794 3644,2794 3644,2817
  region: 4053.88,3231.75 4058.83,3231.75 4058.83,3209.2 4053.88,3209.2 4053.88,3231.75
  region: 3919.99,3032.35 3924.94,3032.35 3924.94,3009.8 3919.99,3009.8 3919.99,3032.35
  region: 3507.29,3270.44 3510.92,3270.44 3510.92,3243.5 3507.29,3243.5 3507.29,3270.44
  region: 3733.1,3232.46 3735.23,3232.46 3735.23,3209.77 3733.1,3209.77 3733.1,3232.46
  region: 4053.94,3335.88 4058.89,3335.88 4058.89,3313.33 4053.94,3313.33 4053.94,3335.88
  region: 3523.29,3428.91 3540.95,3428.91 3540.95,3426.09 3523.29,3426.09 3523.29,3428.91
  region: 2377.11,3174.16 2381.94,3174.16 2381.94,3151.03 2377.11,3151.03 2377.11,3174.16
  region: 3817.05,3287.26 3820.68,3287.26 3820.68,3260.32 3817.05,3260.32 3817.05,3287.26
  region: 4481.17,3301.01 4484.71,3301.01 4484.71,3281.47 4481.17,3281.47 4481.17,3301.01
  region: 3842.17,3181.93 3847,3181.93 3847,3158.8 3842.17,3158.8 3842.17,3181.93
  region: 2146.4,2790.62 2185.45,2790.62 2185.45,2760.38 2146.4,2760.38 2146.4,2790.62
  region: 4054.08,3300.93 4059.03,3300.93 4059.03,3278.38 4054.08,3278.38 4054.08,3300.93
  region: 3757.55,3229.46 3762.74,3229.46 3762.74,3204.5 3757.55,3204.5 3757.55,3229.46
  region: 3416.35,3402.8 3440.05,3402.8 3440.05,3399.02 3416.35,3399.02 3416.35,3402.8
  region: 2452.88,2673.74 2299.39,2520.25 2346.44,2473.2 2500.62,2627.38 2453.56,2674.44 2452.88,2674.44 2452.88,2673.74
  region: 3720.15,3215.01 3741.86,3215.01 3741.86,3212.5 3720.15,3212.5 3720.15,3215.01
  region: 3895.14,3031.02 3898.68,3031.02 3898.68,3011.48 3895.14,3011.48 3895.14,3031.02
  region: 2562.92,2795.69 2593,2795.69 2593,2770.83 2562.92,2770.83 2562.92,2795.69
  region: 2097.39,2699.51 2162.2,2699.51 2162.2,2461.61 2097.39,2461.61 2097.39,2699.51
  region: 4399.62,3324.88 4419.01,3324.88 4419.01,3321.73 4399.62,3321.73 4399.62,3324.88
  region: 4029.23,3299.6 4032.77,3299.6 4032.77,3280.06 4029.23,3280.06 4029.23,3299.6
  region: 3507.22,3165.7 3510.85,3165.7 3510.85,3138.76 3507.22,3138.76 3507.22,3165.7
  region: 4400.67,3298.54 4421.17,3298.54 4421.17,3294.93 4400.67,3294.93 4400.67,3298.54
  region: 3532.1,3270.07 3536.93,3270.07 3536.93,3246.94 3532.1,3246.94 3532.1,3270.07
  region: 3666.68,3422.95 3686.07,3422.95 3686.07,3419.8 3666.68,3419.8 3666.68,3422.95
  region: 4029.09,3334.55 4032.63,3334.55 4032.63,3315.01 4029.09,3315.01 4029.09,3334.55
  region: 3817.36,3182.3 3820.99,3182.3 3820.99,3155.36 3817.36,3155.36 3817.36,3182.3
  region: 4290.95,3266.03 4312.84,3266.03 4312.84,3261.07 4290.95,3261.07 4290.95,3266.03
  region: 3733.12,3131.24 3736.75,3131.24 3736.75,3104.3 3733.12,3104.3 3733.12,3131.24
  region: 4013.74,3217.03 4035.45,3217.03 4035.45,3214.52 4013.74,3214.52 4013.74,3217.03
  region: 3347.07,3386.93 3351.08,3386.93 3351.08,3411.34 3347.07,3411.34 3347.07,3386.93
  region: 2348.35,3174.46 2351.98,3174.46 2351.98,3147.52 2348.35,3147.52 2348.35,3174.46
  region: 3757.93,3130.87 3762.76,3130.87 3762.76,3107.74 3757.93,3107.74 3757.93,3130.87
  region: 3492.05,3095.02 3492.05,3097.02 3473.95,3097.02 3473.95,3095.02 3492.05,3095.02
  region: 2303.62,2930.56 2339.76,2930.56 2339.76,2900.37 2303.62,2900.37 2303.62,2930.56
  region: 4506.02,3302.34 4510.97,3302.34 4510.97,3279.79 4506.02,3279.79 4506.02,3302.34
  region: 3998,2530 4023,2530 4023,2510 3998,2510 3998,2530
  region: 3520.65,3369.94 3542.54,3369.94 3542.54,3364.98 3520.65,3364.98 3520.65,3369.94
  region: 4141.67,3324.76 4161.06,3324.76 4161.06,3321.61 4141.67,3321.61 4141.67,3324.76
  region: 4293.59,3325 4311.25,3325 4311.25,3322.18 4293.59,3322.18 4293.59,3325
  region: 3532.03,3165.33 3536.86,3165.33 3536.86,3142.2 3532.03,3142.2 3532.03,3165.33
  region: 3321.02,3407.17 3324.43,3407.17 3324.43,3387.26 3321.02,3387.26 3321.02,3407.17
  region: 4142.72,3298.42 4163.22,3298.42 4163.22,3294.81 4142.72,3294.81 4142.72,3298.42
  region: 3758.03,3028.52 3762.98,3028.52 3762.98,3005.97 3758.03,3005.97 3758.03,3028.52
  region: 3757.93,3297.17 3762.96,3297.17 3762.96,3275.44 3757.93,3275.44 3757.93,3297.17
  region: 3995,685 4000,685 4000,645 3995,645 3995,685
  region: 4054.03,3129.11 4058.98,3129.11 4058.98,3106.56 4054.03,3106.56 4054.03,3129.11
  region: 4008,2594 4098,2594 4098,2564 4008,2564 4008,2594
  region: 2586.68,2781.98 2607.52,2781.98 2607.52,2752.02 2586.68,2752.02 2586.68,2781.98
  region: 3717.81,3293.92 3738.04,3293.92 3738.04,3289.06 3717.81,3289.06 3717.81,3293.92
  region: 4000,2668 4000,2651 4009,2651 4032,2628 4102,2628 4102,2631.55 4031,2631.55 4011,2655 4004,2655 4004,2659 4116,2659 4116,2668 4000,2668
  region: 3720.19,3318.99 3740.03,3318.99 3740.03,3315.07 3720.19,3315.07 3720.19,3318.99
  region: 4013.66,3192.03 4033.74,3192.03 4033.74,3187.06 4013.66,3187.06 4013.66,3192.03
  region: 1916.5,2149.5 1916.5,2136.5 1918.5,2136.5 1918.5,2149.5 1916.5,2149.5
  region: 1258.5,2382.5 1263.5,2382.5 1263.5,2367.5 1258.5,2367.5 1258.5,2382.5
  region: 4184,2668 4184,2614 4096,2614 4096,2630 4102,2630 4102,2620 4176,2620 4176,2662 4113,2662 4113,2668 4184,2668
Inner Layer 3:
  region: 3958.55,2631 4014,2631 4014,2596.54 3964.55,2596.54 3958.55,2602.54 3958.55,2631
  region: 3958.55,2631 4014,2631 4014,2596.54 3964.55,2596.54 3958.55,2602.54 3958.55,2631
  region: 3104.37,2267.78 3107.43,2267.78 3107.43,2250.03 3104.37,2250.03 3104.37,2267.78
  region: 4045.79,2666.5 4101.79,2666.5 4101.79,2630.22 4045.79,2630.22 4045.79,2666.5
  region: 4045.79,2666.5 4101.79,2666.5 4101.79,2630.22 4045.79,2630.22 4045.79,2666.5
Bottom:
  region: 2359,2687 2442,2687 2442,2658 2359,2658 2359,2687
  region: 3948.45,2603 3948.45,2672.4 4106.63,2672.4 4106.63,2590.64 3948.86,2590.64 3948.86,2603 4100.5,2603 4100.5,2665.21 3956.51,2665.21 3956.51,2603 3948.45,2603
  region: 2271,2722 2374,2722 2374,2638 2271,2638 2271,2722
  region: 1906,2756 1970,2756 1970,2727 1906,2727 1906,2756
  region: 2042,2705 2071,2705 2071,2608 2042,2608 2042,2705
  region: 2212,2719 2300,2719 2300,2691 2212,2691 2212,2719
  region: 1966,2749 2069,2749 2069,2665 1966,2665 1966,2749
Inner Layer 2:
  region: 4046.06,2666.51 4102.06,2666.51 4102.06,2630.17 4046.06,2630.17 4046.06,2666.51
  region: 3958.49,2631 4014,2631 4014,2596.57 3964.49,2596.57 3958.49,2602.57 3958.49,2631
Keep-Out Layer:
  the board outline again, w10

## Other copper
Top:
  region net GND: 2550,3079 2831,3079 2831,3047 2550,3047 2550,3079
  region net 12V: 3495,1745 3550,1745 3602.5,1692.5 3602.5,1575 3586.25,1558.75 3530,1558.75 3506.88,1581.88 3506.88,1610 3543.44,1646.56 3543.44,1715 3495,1715 3495,1745
  region net SOC_1.2VD: 2253,1991 2261,1999 2277,1999 2280.5,1995.5 2280.5,1964.5 2278,1962 2260.5,1962 2253,1969.5 2253,1991
  region net GND: 2417,3079 2555,3079 2555,3047 2417,3047 2417,3079
  region net 1.8VD: 839.94,2454 849.94,2464 944,2464 956.5,2451.5 956.5,2284 940.25,2267.75 889,2267.75 880.88,2275.88 880.88,2369 839.94,2409.94 839.94,2454
  region net N16996557: 979,2684 859,2684 838,2663 838,2486 845,2479 987,2479 998,2490 998,2665 979,2684
  region net 12V: 3879,694 3894,679 3994,679 4136.5,821.5 4136.5,1024 4120.25,1040.25 3844,1040.25 3807.12,1077.12 3604,1077.12 3604,1006 3641,969 3789,969 3879,879 3879,694
  region net 3.3V: 4034,1486 4044,1496 4145,1496 4155,1486 4155,1429 4150,1424 4039,1424 4034,1429 4034,1486
  region net N17424413: 3724,1231 3745,1231 3753,1223 3753,1158 3767,1144 3828,1144 3854,1170 3854,1243 3865,1254 3911,1254 3922,1243 3922,1063 3918,1059 3854,1059 3818,1095 3754,1095 3716,1133 3716,1223 3724,1231
  region net N17424778: 3551.25,1960 3561.25,1970 3780,1970 3835,1915 3935,1915 3940,1910 3940,1825 3930,1815 3800,1815 3768.38,1846.62 3768.38,1872.1 3770.56,1874.28 3741,1874 3553.5,1874 3551.25,1876.25 3551.25,1960
  region net 3.3VD: 875.62,3029.38 865,3040 805,3040 795,3030 795,2820 801.25,2813.75 870,2813.75 875.62,2819.38 875.62,3029.38
  region net GND: 1479,2844 1479,3079 1511,3079 1511,2844 1479,2844
  region net GND: 2799,2384 2799,2459 2831,2459 2831,2384 2799,2384
  region net GND: 2000,1509 1479,1509 1479,1541 2000,1541 2000,1509
  region net 12V_L: 4157.59,1029 4167.59,1039 4249,1039 4264,1024 4264,764 4186.5,686.5 4186.5,574 4075.25,462.75 3859,462.75 3843.38,478.38 3843.38,594 3861.19,611.81 3964,611.81 4157.59,805.41 4157.59,1029
  region net GND: 1479,3079 1925,3079 1925,3047 1479,3047 1479,3079
  region net 3.3VD: 2358,2099 2370,2099 2374,2095 2374,2077 2365,2068 2360,2068 2355,2063 2355,2053 2353,2051 2325,2051 2323,2053 2323,2060 2342,2079 2342,2083 2358,2099
  region net GND: 1479,1894 1479,2089 1511,2089 1511,1894 1479,1894
  region net 3.3V: 3985,2145 3900,2145 3887.5,2157.5 3887.5,2340 3985,2340 3985,2145
  region net GND_L: 3864,438.22 3844,418.22 3844,244 3859,229 4099,229 4496.5,626.5 4600.25,626.5 4614,640.25 4614,739 4602.12,750.88 4279,750.88 4215.56,687.44 4215.56,569 4084.78,438.22 3864,438.22
  region net GND: 2799,2524 2799,2823 2831,2823 2831,2524 2799,2524
  region net GND: 1479,2249 1479,2374 1511,2374 1511,2249 1479,2249
  region net GND: 4389,924 4399,934 4604,934 4614,924 4614,779 4604,769 4399,769 4389,779 4389,924
  region net GND: 2799,1509 2799,1970 2831,1970 2831,1509 2799,1509
  region net 3.3VD: 3986.88,2130 3745,2130 3727.5,2112.5 3727.5,2040 3807.5,1960 3968.75,1960 3986.88,1978.12 3986.88,2130
  region net 12V: 3670,1120 3695,1120 3760,1055 3760,1020 3670,1020 3670,1120
  region net N17424411: 4057,1364 4088,1364 4112,1340 4112,1317 4126,1303 4175,1303 4199,1279 4199,1212 4182,1195 4182,1070 4171,1059 4059,1059 4044,1074 4044,1351 4057,1364
  region net GND: 2799,2864 2799,3079 2831,3079 2831,2864 2799,2864
  region net SOC_1.2VD: 2127,2042 2165.5,2042 2173,2034.5 2173,2030 2156,2013 2142,2013 2122,2033 2122,2037 2127,2042
  region net SOC_1.2VD: 2351.5,2148 2371.5,2168 2391,2168 2412,2147 2412,2130 2403,2121 2365,2121 2343,2143 2343,2148 2351.5,2148
  region net 12V: 3700,1180 3695,1185 3670,1185 3655,1170 3655,1125 3647.5,1117.5 3555,1117.5 3555,1020 3575,1000 3700,1000 3700,1180
  region net N17424380: 4174,1455 4174,1405 4227,1352 4227,1197 4198,1168 4198,1136 4346,1136 4448,1238 4448,1293 4430,1311 4372,1311 4219,1464 4183,1464 4174,1455
Inner Layer 3:
  region net 3.3VD: 2063.12,2310 2210,2310 2227.5,2292.5 2227.5,2280 2190,2280 2167.5,2257.5 2167.5,2250 2163.75,2246.25 2090,2246.25 2063.12,2273.12 2063.12,2310
  region net 3.3VD: 1711.4,2653.6 1700,2665 1665,2665 1655,2655 1655,2595 1670,2580 1705,2580 1711.4,2586.4 1711.4,2653.6
Bottom:
  region net SOC_1.2VD: 2267.5,2005 2355,2005 2407.5,1952.5 2407.5,1930 2320,1930 2267.5,1982.5 2267.5,2005
  region net SOC_1.2VD: 2325,1960 2400,1960 2422.5,1937.5 2422.5,1890 2412.5,1880 2340,1880 2325,1895 2325,1960
  region net SOC_1.5VD: 3035,2235 3040,2240 3125,2240 3132.5,2232.5 3132.5,2020 3103.75,1991.25 3103.75,1790 3070,1790 2997.5,1862.5 2997.5,1992.5 3035,2030 3035,2235
  region net 12V: 3585,1430 3580,1435 3515,1435 3510,1430 3510,1385 3515,1380 3580,1380 3585,1385 3585,1430
  region net N17346710: 3935,1764 3935,1701 3943,1693 4127,1693 4157,1663 4287,1663 4298,1674 4298,1695 4287,1706 4203,1706 4145,1764 3935,1764
  region net N17346690: 3935,1950 3935,1886 4159,1886 4199,1846 4271,1846 4302,1815 4338,1815 4356,1833 4356,1952 4337,1971 3956,1971 3935,1950
  region net 3.3VD: 2595,2230 2605,2240 2650,2240 2660,2230 2660,2195 2650,2185 2605,2185 2595,2195 2595,2230
  region net 12V: 3972,1659 4132,1659 4146,1645 4267,1645 4271,1641 4271,1616 4267,1612 4153,1612 4133,1592 3933,1592 3933,1620 3972,1659
Inner Layer 2 (plane layer: these items are gaps in the copper):
  region: 3622,871 3622,109 3555,109 3555,830 3320,1065 740,1065 520,845 520,109 450,109 450,865 724,1139 3354,1139
  lines w5: 74,109 74,3849.16 4719.67,3849.16 4719.67,109 3622,109 3622,871 3354,1139 724,1139 450,865 450,109 74,109 ; 520,109 520,845 740,1065 3320,1065 3555,830 3555,109 520,109
Multi-Layer:
  lines w10: 87,-1462 2807,-1462 ; 87,-1270 2813,-1270 ; 87,-1070 2813,-1070 ; 87,-870 2813,-870 ; 487,-1772 487,-1462 ; 487,-1602 2807,-1602 ; 683,-1462 683,-870 ; 1147,-1772 1147,-1462 ; 1697,-1772 1697,-1462 ; 2163,-1267 2163,-640 ; 2357,-1772 2357,-1462 ; 2643,-1270 2643,-1070 ; 87,-1772 2813,-1772 2813,-640 87,-640 87,-1772
  text "MODEL NAME" at 123,-1000 h50
  text "MT7620A+MT7610E-V10" at 786,-1023 h50
  text "MODEL NO." at 133,-1200 h50
  text "LAYERS" at 2233,-1200 h40
  text "4" at 2703,-1200 h50
  text "LAYER" at 133,-1410 h50
  text "Through Hole Via" at 527,-1562 h40
  text "Plugging Resin" at 1187,-1562 h40
  text "Blind Via" at 1887,-1562 h40
  text "Buried Via" at 2417,-1562 h40
  text "Via Type:" at 127,-1642 h40
  text "Yes" at 757,-1712 h40
  text "No" at 1377,-1712 h40
  text "No" at 1987,-1712 h40
  text "No" at 2547,-1712 h40

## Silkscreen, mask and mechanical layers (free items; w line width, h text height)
Silkscreen Top:
  drawing of 146 lines, arcs and shapes, not listed
  text "USB" at 3187.5,3677 h25
  text "POWER" at 640,3670 h25
  text "LAN1" at 1612.5,3663 h25
  text "WPS" at 990,3661.5 h25
  text "LAN2" at 1940.5,3657 h25
  text "WAN" at 1318,3654 h25
  text "LAN4" at 2562,3654.5 h25
  text "LAN3" at 2208.5,3652 h25
  text "WLAN" at 2942.5,3554 h25
  text "D" at 4652.5,3517.5 h25
  text "WS2334" at 100.5,3431.5 h40
  text "D" at 4037.5,3392.5 h25
  text "H" at 2092.5,3357.5 h25
  text "MT7620A+MT7610E-V10" at 103,3331.5 h40
  text "A" at 2787.5,3287.5 h25
  text "B" at 3782.5,3282.5 h25
  text "W" at 4251.76,3110.64 h25
  text "W" at 3941.65,3080.97 h25
  text "H" at 2189.5,2560 h25
  text "A" at 2292.5,2557.5 h25
  text "C" at 3347.5,2492.5 h25
  text "C" at 3237.5,2352.5 h25
  text "B" at 4582.5,2302.5 h25
  text "1.8V" at 730,2200 h50
  text "F" at 1829.5,2127 h25
  text "WPS" at 151,2094.5 h25
  text "3.3V" at 3970,1985 h25
  text "WS" at 295,1655 h25 r90
  text "F" at 1331,1579 h25
  text "I2C_SDA" at 177,1571 h25 r90
  text "I2C_SCL" at 585,1425 h25 r90
  text "DI" at 241,1424 h25 r90
  text "BCK" at 438.5,1399 h25 r90
  text "DO" at 320,1360 h25 r90
  text "VCC" at 525,1235 h25
  text "RXD" at 520,1135 h25
  text "TXD" at 515,1050 h25
  text "GND" at 520,945 h25
  text "RESET" at 161,933.5 h25
  text "12V" at 3620,270 h50
Silkscreen Bottom:
  lines w5: 1402,1442.5 1402,1739.5 1612.5,1739.5 1612.5,1835 1766.5,1835 1766.5,1559.5 1619.5,1559.5 1619.5,1442.5 1402,1442.5 ; 1455.5,1849 1455.5,2149 1817,2149 1817,1899 1721,1899 1721,1849 1455.5,1849 ; 1876,1671 1878,1671 2044,1837 2198,1683 2031,1516 1876,1671 ; 4451.5,1170 4451.5,1460.5 4534,1460.5 4534,1796 4659,1796 4659,1498.5 4640,1498.5 4640,1170 4451.5,1170
  lines w6: 101,1432 101,3132 106,3137 1126,3137 1126,1382 151,1382 101,1432
  lines w8: 1948.09,3294.47 3247.3,3294.47 3247.3,3570.06 1948.09,3570.06 1948.09,3294.47
  text "SOC_1.2VD" at 3285,1390 h25
  text "SOC_1.5VD" at 3280,1330 h25
Paste Mask Top:
  drawing of 32 lines, arcs and shapes, not listed
Solder Mask Top:
  region: 2799,1509 2799,1970 2831,1970 2831,1509 2799,1509
  region: 1479,1894 1479,2089 1511,2089 1511,1894 1479,1894
  region: 2799,2524 2799,2823 2831,2823 2831,2524 2799,2524
  region: 1479,2844 1479,3079 1511,3079 1511,2844 1479,2844
  region: 2799,2864 2799,3079 2831,3079 2831,2864 2799,2864
  region: 1479,2249 1479,2374 1511,2374 1511,2249 1479,2249
  region: 2417,3079 2555,3079 2555,3047 2417,3047 2417,3079
  region: 2799,2384 2799,2459 2831,2459 2831,2384 2799,2384
  region: 2000,1509 1479,1509 1479,1541 2000,1541 2000,1509
  region: 1479,3079 1925,3079 1925,3047 1479,3047 1479,3079
  region: 2550,3079 2831,3079 2831,3047 2550,3047 2550,3079
Assembly Drawing Bottom:
  drawing of 784 lines, arcs and shapes, not listed
Layer_16:
  drawing of 377 lines, arcs and shapes, not listed
Drill Drawing:
  lines w1: 74,3849.16 74.03,3849.16 ; 4719.67,109 4719.7,109 ; 4719.67,3849.16 4719.7,3849.16 4719.67,3849.16
  lines w10: 74,3899.16 74,4194 ; 2205.47,4144 74,4144 ; 2588.2,4144 4719.67,4144 ; 4719.67,3899.16 4719.67,4194 ; 4769.67,109 5080.5,109 ; 4769.67,3849.16 5080.5,3849.16 ; 5030.5,1911.58 5030.5,109 ; 5030.5,2046.58 5030.5,3849.16 ; 74,4144 174,4119 174,4169 74,4144 ; 4719.67,4144 4619.67,4169 4619.67,4119 4719.67,4144 ; 5030.5,109 5055.5,209 5005.5,209 5030.5,109 ; 5030.5,3849.16 5005.5,3749.16 5055.5,3749.16 5030.5,3849.16
  text "118.0mm" at 2235.47,4106.5 h50
  text "95.0mm" at 4874.82,1941.58 h50
Layer_19:
  lines w10: 2808.15,-1770.63 4428.15,-1770.63 4428.15,-640.63 2813.15,-640.63 ; 2812.04,-1601.65 4427.22,-1601.65 ; 2812.23,-869.8 4424.7,-869.8 ; 2812.55,-1269.74 4427.68,-1269.74 ; 2812.61,-1461.49 4426.89,-1461.49 ; 2812.67,-1069.53 4427.79,-1069.53 ; 3088.15,-865.83 3088.15,-645.63 ; 3833.15,-1768.67 3833.15,-870.79 ; 4133.15,-1765.63 4133.15,-873.51 ; 4777.45,-1615.05 6407.45,-1615.05 ; 4777.45,-1505.05 6407.45,-1505.05 ; 4777.45,-1395.05 6407.45,-1395.05 ; 4777.45,-1285.05 6407.45,-1285.05 ; 4777.45,-1175.05 6407.45,-1175.05 ; 4777.45,-1065.05 6407.45,-1065.05 ; 4777.45,-955.05 6407.45,-955.05 ; 4777.45,-845.05 6407.45,-845.05 ; 5927.45,-1725.05 5927.45,-705.05 ; 4777.45,-1725.05 4777.45,-705.05 6407.45,-705.05 6407.45,-1725.05 4777.45,-1725.05
  text "Update Footprint Table" at 4797.45,-655.05 h50
  text "Footprint Name" at 5067.45,-795.05 h40
  text "Update Date" at 5967.45,-795.05 h40
  text "DDR/PCIE/USB/PHY_IC/PHY_ETH/RF" at 3172,-800.5 h25
  text "Class" at 2836.58,-803.93 h50
  text "2013/7/4" at 6092.5,-912 h25
  text "R/L/C0402" at 5046.5,-916 h25
  text "Via" at 4223.15,-1000.63 h50
  text "Component Ref" at 3043.63,-1002.91 h50
  text "W/St" at 3883.15,-1015.63 h50
  text "2013/7/4" at 6097.5,-1022 h25
  text "SB/1206" at 5051.5,-1023.5 h25
  text "2013/7/4" at 6101,-1133 h25
  text "FD" at 5066,-1136 h25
